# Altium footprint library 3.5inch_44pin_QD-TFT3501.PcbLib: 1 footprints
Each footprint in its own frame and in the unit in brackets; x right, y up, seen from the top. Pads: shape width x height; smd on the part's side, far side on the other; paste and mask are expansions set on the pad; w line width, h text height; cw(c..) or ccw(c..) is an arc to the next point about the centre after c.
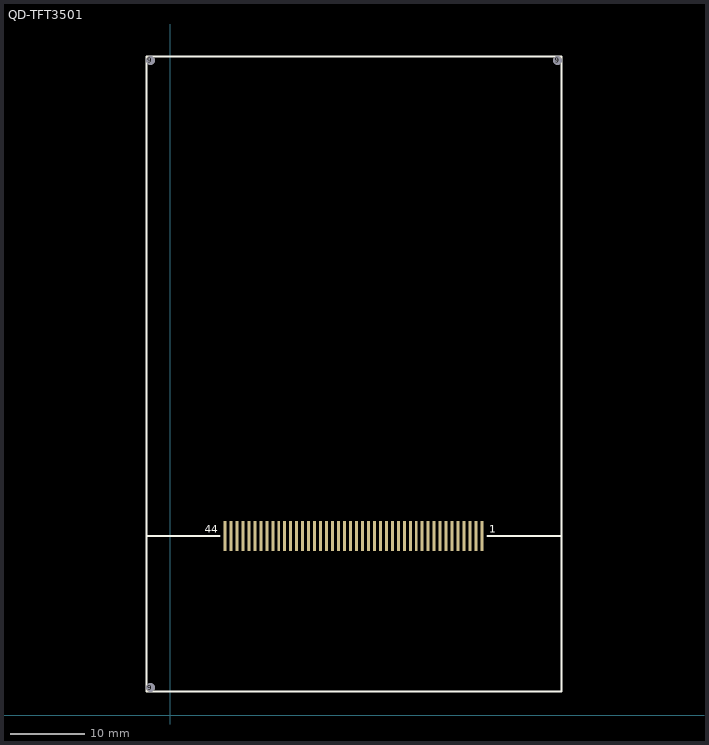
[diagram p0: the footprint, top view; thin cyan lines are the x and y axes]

## QD-TFT3501 [mm] "3.5inch TFT LCD"
pads (48):
  rect 0.4x4 smd: 1(40.905,23.975) 1(41.705,23.975) 3(40.105,23.975) 4(39.305,23.975) 5(38.505,23.975) 6(37.705,23.975) 7(36.905,23.975) 8(36.105,23.975) 9(35.305,23.975) 10(34.505,23.975) 11(33.705,23.975) 12(32.905,23.975) 13(32.105,23.975) 14(31.305,23.975) 15(30.505,23.975) 16(29.705,23.975) 17(28.905,23.975) 18(28.105,23.975) 19(27.305,23.975) 20(26.505,23.975) 21(25.705,23.975) 22(24.905,23.975) 23(24.105,23.975) 24(23.305,23.975) 25(22.505,23.975) 26(21.705,23.975) 27(20.905,23.975) 28(20.105,23.975) 29(19.305,23.975) 30(18.505,23.975) 31(17.705,23.975) 32(16.905,23.975) 33(16.105,23.975) 34(15.305,23.975) 35(14.505,23.975) 36(13.705,23.975) 37(12.905,23.975) 38(12.105,23.975) 39(11.305,23.975) 40(10.505,23.975) 41(9.705,23.975) 42(8.905,23.975) 43(8.105,23.975) 44(7.305,23.975) 44(7.305,23.975)
  round 1.2 hole 1.2 unplated mask+0: 9(-2.675,3.675) 9(-2.675,87.635) 9(51.825,87.635)
Top Overlay:
  lines w0.254: -3.147,23.975 6.604,23.975 ; 42.418,23.975 52.297,23.975 ; -3.175,3.175 52.325,3.175 52.325,88.135 -3.175,88.135 -3.175,3.175
  text "44" at 4.572,24.384 h1.02
  text "1" at 42.672,24.384 h1.02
